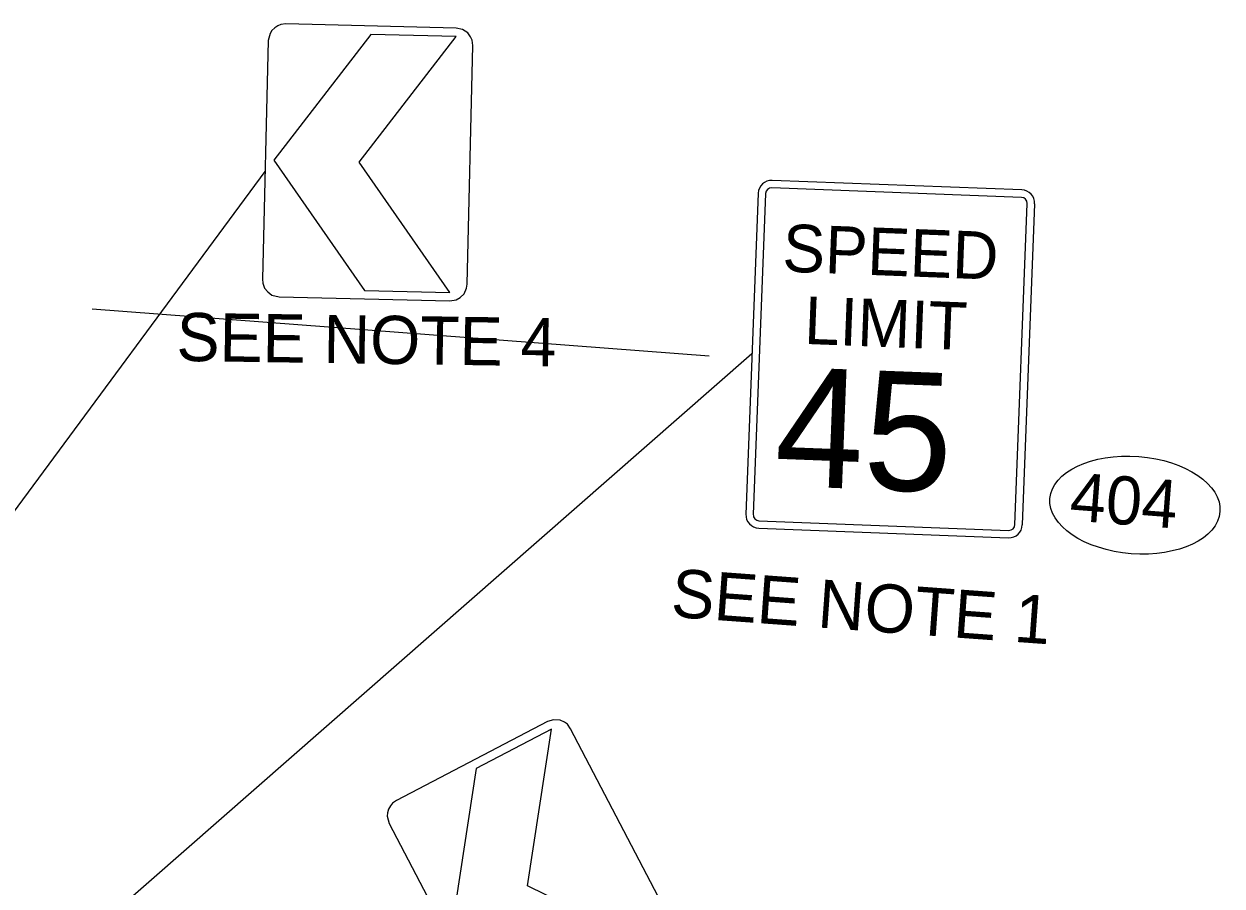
# Model space of a CAD drawing. Extents: x 2096670 to 2098561, y 684033 to 689893.
# Drawn here: x 2097772.9 to 2098071.1, y 686186.8 to 686401.4 of the extents above; entities that cross this region are included whole.
import ezdxf

# ---------------------------------------------------------------- set-up
doc = ezdxf.new("R2010")
doc.units = 0
for name, color, linetype in [('Default', 7, 'Continuous'), ('Exist Sign E Chevron Left', 7, 'Continuous'), ('Prop DSN Text', 7, 'Continuous'), ('Prop Sign E One Way_Right CELL', 7, 'Continuous'), ('Scratch_Level_3', 7, 'Continuous')]:
    doc.layers.add(name, color=color, linetype=linetype)

msp = doc.modelspace()

# ---------------------------------------------------------------- linework, layer by layer
at = {"layer": 'Default'}
for p, q in [((2098021.25, 686360.06), (2097959.1, 686362.44)), ((2097955.64, 686359.24), (2097952.57, 686279.32)), ((2097957.49, 686359.17), (2097954.42, 686279.25)), ((2098021.18, 686358.21), (2097959.02, 686360.59)), ((2098019.54, 686276.75), (2098022.61, 686356.67)), ((2098021.39, 686276.68), (2098024.46, 686356.6)), ((2097954.1, 686319.28), (2097755.4, 686145.31)), ((2097955.77, 686275.87), (2098017.93, 686273.48)), ((2097955.84, 686277.72), (2098018, 686275.33))]:
    msp.add_line(p, q, dxfattribs=at)
for centre, radius, start, end in [((2097958.97, 686359.11), 3.33, 87.8009, 177.8009), ((2097958.97, 686359.11), 1.48, 87.8009, 177.8009), ((2098021.13, 686356.73), 3.33, 357.8009, 87.8009), ((2098021.13, 686356.73), 1.48, 357.8009, 87.8009), ((2097955.9, 686279.2), 3.33, 177.8009, 267.8009), ((2097955.9, 686279.2), 1.48, 177.8009, 267.8009), ((2098018.06, 686276.81), 3.33, 267.8009, 357.8009), ((2098018.06, 686276.81), 1.48, 267.8009, 357.8009)]:
    msp.add_arc(centre, radius, start, end, dxfattribs=at)
at = {"layer": 'Exist Sign E Chevron Left'}
for p, q in [((2097856.32, 686366.95), (2097856.32, 686366.95)), ((2097707.06, 686194.24), (2097832.92, 686364.65)), ((2097898.25, 686186.85), (2097898.25, 686186.85))]:
    msp.add_line(p, q, dxfattribs=at)
for points in [[(2097883.21, 686336.58), (2097884.64, 686396), (2097884.47, 686397.36), (2097884.08, 686398.19), (2097883.36, 686399.12), (2097882.02, 686400), (2097880.5, 686400.34), (2097838.06, 686401.37), (2097836.86, 686401.23), (2097836.07, 686400.91), (2097835.31, 686400.41), (2097834.62, 686399.75), (2097834.16, 686399.01), (2097833.71, 686397.23), (2097832.28, 686337.81), (2097832.32, 686336.85), (2097832.8, 686335.65), (2097833.56, 686334.68), (2097834.6, 686333.91), (2097836.42, 686333.46), (2097878.86, 686332.44), (2097880.5, 686332.7), (2097881.5, 686333.29), (2097882.44, 686334.22), (2097883.01, 686335.63), (2097883.21, 686336.58)], [(2097936.48, 686173.29), (2097908.97, 686225.97), (2097908.16, 686227.08), (2097907.42, 686227.61), (2097906.34, 686228.08), (2097904.74, 686228.2), (2097903.24, 686227.77), (2097865.61, 686208.11), (2097864.64, 686207.41), (2097864.1, 686206.75), (2097863.67, 686205.95), (2097863.39, 686205.04), (2097863.34, 686204.17), (2097863.81, 686202.39), (2097891.33, 686149.7)]]:
    msp.add_lwpolyline(points, dxfattribs=at)
for points in [[(2097878.91, 686334.54), (2097856.32, 686366.95), (2097880.45, 686398.21), (2097859.22, 686398.72), (2097835.1, 686367.47), (2097857.69, 686335.05)], [(2097933.71, 686169.42), (2097898.25, 686186.85), (2097904.23, 686225.87), (2097885.42, 686216.04), (2097879.44, 686177.02), (2097914.9, 686159.6)]]:
    msp.add_lwpolyline(points, close=True, dxfattribs=at)
at = {"layer": 'Prop Sign E One Way_Right CELL'}
msp.add_ellipse((2098049.42, 686281.62), major_axis=(21.16, -1.63), ratio=0.571429, dxfattribs=at)
at = {"layer": 'Scratch_Level_3'}
msp.add_line((2097789.86, 686330.48), (2097943.46, 686318.81), dxfattribs=at)

# ---------------------------------------------------------------- texts
at = {"layer": 'Default'}
for s, height, p in [('SPEED', 11.848, (2097961.54, 686339.75)), ('LIMIT', 11.848, (2097966.96, 686321.75)), ('45', 29.621, (2097959.47, 686286.47))]:
    msp.add_text(s, height=height, rotation=357.8009, dxfattribs=at).set_placement(p)
at = {"layer": 'Prop DSN Text'}
for s, rotation, p in [('SEE NOTE 4', 359.1669, (2097810.82, 686317.52)), ('SEE NOTE 1', 355.8227, (2097933.73, 686253.85))]:
    msp.add_text(s, height=12, rotation=rotation, dxfattribs=at).set_placement(p)
at = {"layer": 'Prop Sign E One Way_Right CELL'}
msp.add_text('404', height=11.98, rotation=355.6034, dxfattribs=at).set_placement((2098032.94, 686277.83))

doc.saveas('drawing.dxf')
